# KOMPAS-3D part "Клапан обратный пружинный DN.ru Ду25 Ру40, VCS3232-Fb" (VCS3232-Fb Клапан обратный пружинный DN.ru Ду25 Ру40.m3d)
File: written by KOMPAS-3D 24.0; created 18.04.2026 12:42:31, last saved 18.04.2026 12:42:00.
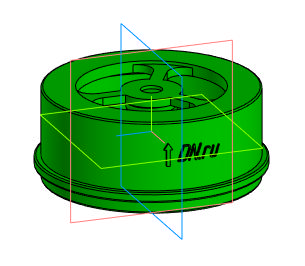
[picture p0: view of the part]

Document properties: Автор: 712; Полное имя файла: C:\Users\712\Desktop\Новая папка (4)\VCS3232-Fb Клапан обратный пружинный DN.ru Ду25 Ру40.m3d

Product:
- Component: Пружина 1086-0796 ГОСТ 18793-80  | qty 1  | additional columns: 3953604318-4147491677-0; Деталь; Пользователь Windows; c; Шероховатость не задана; Да; Сталь 10  ГОСТ 1050-88; source file: Деталь.m3d
- Body: Тело 1  | qty 1
    Масса: 0.271999
- Part/product: Клапан обратный пружинный DN.ru Ду25 Ру40  | designation VCS3232-Fb
    Масса: 0.36
    Раздел спецификации: Прочие изделия
    Примечание: D100-03888
    additional columns: 071bd168-1a06-425c-849c-e99e84a96128; Деталь; 712; c; Шероховатость не задана; Да

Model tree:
1. Операция без истории:2

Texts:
  VCS3232-Fb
